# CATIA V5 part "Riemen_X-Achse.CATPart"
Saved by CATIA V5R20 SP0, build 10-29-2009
Part number: Riemen_X-Achse
Bounding box of the stored display mesh (mm): x 0 to 9, y -710 to 710, z -62 to 20
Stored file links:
  C:\Users\Andi\Desktop\Offene Projekte\Plasmacutter\Rahmen\Riemen_X-Achse.CATPart
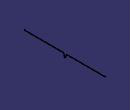
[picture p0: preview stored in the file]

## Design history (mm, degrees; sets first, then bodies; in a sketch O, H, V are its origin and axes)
Body1 (main body)
  Sketch1 on yz-plane, origin (0, 0, 0), H (0, 1, 0), V (0, 0, 1)
    arc A1 centre (0, -53) radius 9 from (-8.6781, -55.3854) to (8.6781, -55.3854) ccw
    point P1 (0, -53)
    line L1 (8.6781, -55.3854) -> (22.2861, -5.8796)
    point P4 (23.9023, 0)
    line L2 (30, 0) -> (707, 0)
    line L3 (-8.6781, -55.3854) -> (-22.2861, -5.8796)
    point P5 (-23.9023, 0)
    line L4 (-30, 0) -> (-707, 0)
    arc A2 centre (-30, -8) radius 8 from (-22.2861, -5.8796) to (-30, 0) ccw
    point P8 (-30, -8)
    arc A3 centre (30, -8) radius 8 from (22.2861, -5.8796) to (30, 0) cw
    point P11 (30, -8)
    line L5 (710, 3) -> (710, 20)
    line L6 (-710, 3) -> (-710, 20)
    arc A4 centre (-707, 3) radius 3 from (-707, 0) to (-710, 3) cw
    point P15 (-710, 20)
    point P16 (710, 20)
    arc A5 centre (707, 3) radius 3 from (707, 0) to (710, 3) ccw
    distance P1 H = 53
    radius A2 = 8
    distance P11 P8 = 60
    radius A1 = 9
    radius A4 = 3
    distance L5 L6 = 1420
    distance P15 L4 = 20
    distance P16 L2 = 20 {= Sketch1.distance(P15 L4)}
    coincidence: P1 V, P4 H, P5 H, L3 P5, L4 P5, L1 P4, L2 P4
    tangency: L1 A1, L3 A1, A2 L3, A2 L4, A3 L1, A3 L2, A4 L4, A4 L6, A5 L2, A5 L5
    horizontal: L2 H, L4 H
    symmetry: A3 A2 V, A4 A5 V
    vertical: L5 V, L6 V
  Pad1: profile Sketch1, direction (1, 0, 0), length 9, thin wall 2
